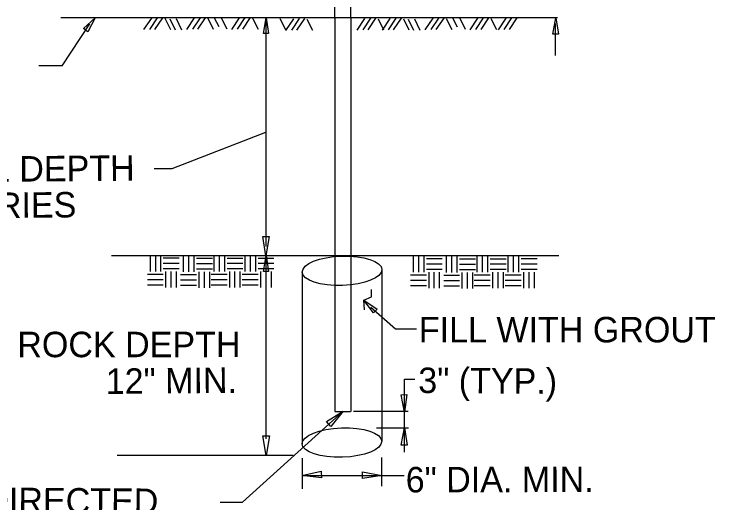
# Model space of a CAD drawing. Extents: x 0 to 1270, y 0 to 830.
# Drawn here: x 332.3 to 468.6, y 95.4 to 190.4 of the extents above; entities that cross this region are included whole.
import ezdxf

# ---------------------------------------------------------------- set-up
doc = ezdxf.new("R2010")
doc.units = 0
for name, color, linetype in [('CT_Dimensions', 7, 'Continuous'), ('Grout', 7, 'Continuous'), ('Rock Pattern', 7, 'Continuous'), ('sb_Dimension Lines', 7, 'Continuous'), ('sb_Earth', 7, 'Continuous'), ('sb_Existing Structural Steel', 7, 'Continuous')]:
    doc.layers.add(name, color=color, linetype=linetype)

# ---------------------------------------------------------------- blocks, each defined once
blk = doc.blocks.new('Dimension Terminator')
at = {"layer": 'sb_Dimension Lines'}
blk.add_lwpolyline([(-4.76, 0.79), (0, 0), (-4.76, -0.79)], close=True, dxfattribs=at)

msp = doc.modelspace()

# ---------------------------------------------------------------- linework, layer by layer
at = {"layer": 'CT_Dimensions'}
for p, q in [((381.24, 189.6), (381.24, 145.19)), ((341.64, 180.29), (347, 188.43)), ((437.56, 182.33), (437.56, 188.54)), ((341.64, 180.29), (337.06, 180.29)), ((362.98, 160.36), (381.24, 167.39)), ((359.49, 160.36), (362.98, 160.36)), ((381.24, 143.37), (381.24, 107.86)), ((401.76, 135.44), (401.79, 136.84)), ((400.28, 134.77), (401.76, 135.44)), ((400.41, 132.87), (400.28, 134.77)), ((406.41, 129.16), (401.66, 133.37)), ((410.5, 129.16), (406.41, 129.16)), ((408.2, 105.25), (408.17, 119.44)), ((408.17, 119.44), (410.21, 119.44)), ((408.87, 113.14), (398.29, 113.14)), ((376.68, 95.53), (396.17, 113.12)), ((402.73, 109.98), (408.94, 109.98)), ((352.29, 104.67), (386.52, 104.67)), ((388.25, 104.09), (388.25, 98.13)), ((403.73, 104.19), (403.73, 98.62)), ((388.22, 100.72), (408.09, 100.72)), ((372.36, 95.53), (376.68, 95.53))]:
    msp.add_line(p, q, dxfattribs=at)
msp.add_lwpolyline([(437.05, 186.48), (437.58, 189.62), (438.1, 186.48)], close=True, dxfattribs=at)
at = {"layer": 'Grout'}
for p, q in [((403.79, 140.72), (403.74, 107.36)), ((388.31, 140.23), (388.26, 106.86))]:
    msp.add_line(p, q, dxfattribs=at)
for centre in [(396.05, 140.48), (396, 107.11)]:
    msp.add_ellipse(centre, major_axis=(7.74, 0.25), ratio=0.369123, dxfattribs=at)
at = {"layer": 'Rock Pattern'}
for p, q in [((438.2, 143.37), (351.23, 143.39)), ((358.7, 143.42), (358.7, 140.33)), ((359.73, 143.42), (359.73, 140.33)), ((360.76, 143.42), (360.76, 140.33)), ((365.16, 143.37), (365.16, 140.28)), ((366.19, 143.37), (366.19, 140.28)), ((367.22, 143.37), (367.22, 140.28)), ((371.1, 143.41), (371.1, 140.32)), ((372.13, 143.41), (372.13, 140.32)), ((373.16, 143.41), (373.16, 140.32)), ((377.13, 143.42), (377.13, 140.33)), ((378.16, 143.42), (378.16, 140.33)), ((379.19, 143.42), (379.19, 140.33)), ((409.85, 143.3), (409.85, 140.21)), ((410.88, 143.3), (410.88, 140.21)), ((411.91, 143.3), (411.91, 140.21)), ((416.31, 143.25), (416.31, 140.16)), ((417.34, 143.25), (417.34, 140.16)), ((418.37, 143.25), (418.37, 140.16)), ((422.25, 143.29), (422.25, 140.2)), ((423.29, 143.29), (423.29, 140.2)), ((424.32, 143.29), (424.32, 140.2)), ((428.29, 143.3), (428.29, 140.21)), ((429.32, 143.3), (429.32, 140.21)), ((430.35, 143.3), (430.35, 140.21)), ((364.36, 142.91), (361.27, 142.91)), ((364.36, 141.88), (361.27, 141.88)), ((370.82, 142.86), (367.73, 142.86)), ((370.82, 141.83), (367.73, 141.83)), ((376.76, 142.9), (373.67, 142.9)), ((376.76, 141.87), (373.67, 141.87)), ((382.8, 142.9), (379.71, 142.9)), ((382.8, 141.87), (379.71, 141.87)), ((415.52, 142.78), (412.43, 142.78)), ((415.52, 141.75), (412.43, 141.75)), ((421.98, 142.73), (418.89, 142.73)), ((427.92, 142.77), (424.83, 142.77)), ((433.96, 142.78), (430.87, 142.78)), ((433.96, 141.75), (430.87, 141.75)), ((364.36, 140.85), (361.27, 140.85)), ((370.82, 140.8), (367.73, 140.8)), ((376.76, 140.84), (373.67, 140.84)), ((382.8, 140.84), (379.71, 140.84)), ((415.52, 140.72), (412.43, 140.72)), ((421.98, 141.7), (418.89, 141.7)), ((421.98, 140.67), (418.89, 140.67)), ((427.92, 141.74), (424.83, 141.74)), ((427.92, 140.71), (424.83, 140.71)), ((433.96, 140.72), (430.87, 140.72)), ((358.18, 139.81), (361.27, 139.81)), ((361.79, 137.24), (361.79, 140.33)), ((362.82, 137.24), (362.82, 140.33)), ((363.85, 137.24), (363.85, 140.33)), ((364.64, 139.77), (367.73, 139.77)), ((368.25, 137.19), (368.25, 140.28)), ((369.28, 137.19), (369.28, 140.28)), ((370.31, 137.19), (370.31, 140.28)), ((370.58, 139.81), (373.67, 139.81)), ((374.19, 137.23), (374.19, 140.32)), ((375.22, 137.23), (375.22, 140.32)), ((376.25, 137.23), (376.25, 140.32)), ((376.62, 139.81), (379.71, 139.81)), ((380.22, 137.24), (380.22, 140.33)), ((381.25, 137.24), (381.25, 140.33)), ((382.29, 137.24), (382.29, 140.33)), ((409.34, 139.69), (412.43, 139.69)), ((412.95, 137.12), (412.95, 140.21)), ((413.98, 137.12), (413.98, 140.21)), ((415.01, 137.12), (415.01, 140.21)), ((415.8, 139.64), (418.89, 139.64)), ((419.4, 137.07), (419.4, 140.16)), ((420.43, 137.07), (420.43, 140.16)), ((421.46, 137.07), (421.46, 140.16)), ((421.74, 139.68), (424.83, 139.68)), ((425.35, 137.11), (425.35, 140.2)), ((426.38, 137.11), (426.38, 140.2)), ((427.41, 137.11), (427.41, 140.2)), ((427.78, 139.69), (430.87, 139.69)), ((431.38, 137.11), (431.38, 140.21)), ((432.41, 137.11), (432.41, 140.21)), ((433.44, 137.11), (433.44, 140.21)), ((358.18, 138.78), (361.27, 138.78)), ((358.18, 137.75), (361.27, 137.75)), ((364.64, 138.74), (367.73, 138.74)), ((364.64, 137.71), (367.73, 137.71)), ((370.58, 138.77), (373.67, 138.77)), ((370.58, 137.74), (373.67, 137.74)), ((376.62, 138.78), (379.71, 138.78)), ((376.62, 137.75), (379.71, 137.75)), ((409.34, 138.66), (412.43, 138.66)), ((415.8, 138.61), (418.89, 138.61)), ((421.74, 138.65), (424.83, 138.65)), ((427.78, 138.66), (430.87, 138.66)), ((409.34, 137.63), (412.43, 137.63)), ((415.8, 137.58), (418.89, 137.58)), ((421.74, 137.62), (424.83, 137.62)), ((427.78, 137.63), (430.87, 137.63))]:
    msp.add_line(p, q, dxfattribs=at)
at = {"layer": 'sb_Earth'}
for p, q in [((437.94, 189.62), (341.37, 189.64)), ((358.96, 189.59), (357.46, 187.34)), ((360.09, 189.64), (358.59, 187.39)), ((361.1, 189.64), (359.6, 187.39)), ((361.59, 189.54), (362.66, 187.39)), ((363.75, 189.47), (364.83, 187.32)), ((367.31, 189.6), (365.81, 187.35)), ((368.43, 189.65), (366.93, 187.4)), ((369.45, 189.65), (367.95, 187.4)), ((369.93, 189.54), (371, 187.4)), ((371.16, 189.62), (372.05, 187.94)), ((372.56, 189.65), (373.63, 187.51)), ((376.01, 189.61), (374.51, 187.36)), ((377.14, 189.66), (375.64, 187.41)), ((378.16, 189.66), (376.66, 187.41)), ((378.64, 189.55), (379.71, 187.41)), ((383.94, 189.48), (385.01, 187.34)), ((387.69, 189.49), (386.19, 187.24)), ((388.71, 189.49), (387.21, 187.24)), ((400.43, 189.49), (398.93, 187.24)), ((401.55, 189.54), (400.05, 187.29)), ((402.57, 189.54), (401.07, 187.29)), ((405.35, 189.51), (403.86, 187.26)), ((406.48, 189.57), (404.98, 187.32)), ((407.5, 189.57), (406, 187.32)), ((407.98, 189.46), (409.05, 187.32)), ((413.66, 189.53), (412.16, 187.28)), ((414.79, 189.59), (413.29, 187.34)), ((415.8, 189.59), (414.3, 187.34)), ((416.29, 189.48), (417.36, 187.34)), ((417.52, 189.64), (418.4, 187.87)), ((418.91, 189.59), (419.98, 187.44)), ((422.37, 189.55), (420.87, 187.3)), ((423.49, 189.6), (421.99, 187.35)), ((424.51, 189.6), (423.01, 187.35)), ((424.99, 189.49), (426.06, 187.35)), ((427.87, 189.56), (426.37, 187.31)), ((428.99, 189.62), (427.49, 187.37)), ((430.01, 189.62), (428.51, 187.37)), ((362.53, 189.45), (363.6, 187.31)), ((386.57, 189.44), (385.07, 187.19)), ((389.19, 189.39), (390.26, 187.24)), ((403.05, 189.43), (404.12, 187.29)), ((408.88, 189.39), (409.95, 187.24)), ((410.11, 189.4), (411.18, 187.26))]:
    msp.add_line(p, q, dxfattribs=at)
at = {"layer": 'sb_Existing Structural Steel'}
for p, q in [((394.65, 189.5), (394.7, 259.71)), ((397.75, 189.57), (397.8, 259.71)), ((394.65, 189.5), (394.62, 113.17)), ((397.75, 189.57), (397.72, 113.17)), ((394.63, 113.15), (397.68, 113.15))]:
    msp.add_line(p, q, dxfattribs=at)

# ---------------------------------------------------------------- block references
at = {"layer": 'CT_Dimensions'}
for p, xscale, yscale, rotation in [((348.06, 189.65), 0.6445448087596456, 0.6445448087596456, 52.45271937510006), ((381.25, 189.65), 0.6445448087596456, 0.6445448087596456, 90), ((400.28, 134.77), 0.6445448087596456, 0.6445448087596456, 136.85568054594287), ((408.18, 112.99), 0.7161608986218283, 0.7161608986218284, -88.15281728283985), ((396.28, 113.18), 0.7957343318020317, 0.7957343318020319, 40.918710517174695), ((408.19, 110), 0.7161608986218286, 0.7161608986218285, 88.91083049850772), ((381.28, 104.62), 0.7957343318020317, 0.7957343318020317, -90), ((388.24, 100.72), 0.7957343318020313, 0.7957343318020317, -177.3724751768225), ((403.79, 100.72), 0.7957343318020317, 0.7957343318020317, -0.7264294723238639)]:
    msp.add_blockref('Dimension Terminator', p, dxfattribs=dict(at, xscale=xscale, yscale=yscale, rotation=rotation))
at = {"layer": 'Rock Pattern'}
for p, xscale, yscale, rotation in [((381.24, 143.37), 0.7957343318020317, 0.7957343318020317, -90), ((381.25, 143.44), 0.6445448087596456, 0.6445448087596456, 90)]:
    msp.add_blockref('Dimension Terminator', p, dxfattribs=dict(at, xscale=xscale, yscale=yscale, rotation=rotation))

# ---------------------------------------------------------------- texts
at = {"layer": 'CT_Dimensions'}
for s, rotation, p in [('SOIL DEPTH', 0.4595, (316.37, 157.67)), ('  VARIES', 0.4595, (316.43, 150.63)), ('ROCK DEPTH', 0.0158, (332.89, 123.69)), ('12" MIN.', 0.5238, (350.11, 116.54)), ('3" (TYP.)', 359.6101, (410.84, 116.74)), ('6" DIA. MIN.', 0.1283, (408.42, 97.42)), ('CUT FENCE POST AS DIRECTED', 359.6101, (256.22, 93.92))]:
    msp.add_text(s, height=4.95, rotation=rotation, dxfattribs=at).set_placement(p)
msp.add_text('FILL WITH GROUT', height=4.95, dxfattribs=at).set_placement((410.97, 126.57))

doc.saveas('drawing.dxf')
